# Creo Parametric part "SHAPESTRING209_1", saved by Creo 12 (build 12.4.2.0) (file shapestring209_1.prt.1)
Units: Custom; MM, KILOGRAM, SECS

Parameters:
  PTC_WM_ITERATION = "0"
  PTC_WM_VERSION = "-.0"
  PTC_WM_LIFECYCLE_STATE = "In Work"
  PTC_WM_LIFECYCLE = "MO_CADDocument"
  PTC_WM_CREATED_BY = "Maximilian Roepper (Z0017RMS: MO)"
  PTC_WM_CREATED_ON = "18-Sep-26 11:36:42 AM"
  PTC_WM_MODIFIED_BY = "Maximilian Roepper (Z0017RMS: MO)"
  PTC_WM_MODIFIED_ON = "18-Sep-26 11:36:46 AM"
  PDMLINKNUMBER = "PDM000071454899"
  PTC_WM_NAME = "shapestring209_1.prt"
  PTC_WM_NUMBER = "PDM000071454899"

Other parameters: WEIGHT, WEIGHT_FACTOR, WEIGHT_ADD, _MASS_TEMP, _DIFF_TEMP, MC_ERRORS, SUPPLIER

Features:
  1. coordinate system
  2. datum plane "PRT_YZ"
  3. datum plane "PRT_XY"
  4. datum plane "PRT_XZ"
  5. coordinate system
  6. datum axis
  7. datum axis
  8. datum axis
  9. coordinate system
  10. imported feature

Other named items: PRT, SIEMENS_MO, DRW_VIEW_ORG, PRT_X, PRT_Y, PRT_Z, CS0, ROUGH_GROB

Layers: 00_STD_CSYS-KSYS, 01_STD_PLANES-EBENEN, 02_STD_AXES-ACHSEN, 03_STD_CSYS-KSYS, 24_IMPORT_FEAT-IMPORT_KE, INTFCLR

Surfaces: 1 plane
